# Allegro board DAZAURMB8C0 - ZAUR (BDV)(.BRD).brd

Outline 225.17 x 128 mm; copper layers: TOP, SGND, IN1, IN2, SVCC, IN3, SGND1, BOTTOM. Coordinates in mm from the lower left corner of the outline.

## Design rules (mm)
constraint set DEFAULT: min track width 0.102
net group W10-T123B: nets N17003186 N27752748
net group DFP-S3.5W4(3.5)-T13B: nets CLKA0 CLKA0B CLKA1 CLKA1B M_A_DQSN0 M_A_DQSN1 M_A_DQSN2 M_A_DQSN3 M_A_DQSN4 M_A_DQSN5 M_A_DQSN6 M_A_DQSN7 M_A_DQSP0 M_A_DQSP1 M_A_DQSP2 M_A_DQSP3 M_A_DQSP4 M_A_DQSP5 M_A_DQSP6 M_A_DQSP7 M_B_DQSN0 M_B_DQSN1 M_B_DQSN2 M_B_DQSN3 M_B_DQSN4 M_B_DQSN5 M_B_DQSN6 M_B_DQSN7 M_B_DQSP0 M_B_DQSP1 M_B_DQSP2 M_B_DQSP3 M_B_DQSP4 M_B_DQSP5 M_B_DQSP6 M_B_DQSP7 WCKA0_0 WCKA0_1 WCKA0B_0 WCKA0B_1 WCKA1_0 WCKA1_1 WCKA1B_0 WCKA1B_1
net group DFP-S4.5W4(3.5)-T13B: nets C_IN_CLK C_IN_CLK# C_IN_D0 C_IN_D0# C_IN_D1 C_IN_D1# C_IN_D2 C_IN_D2# C_TX0_HDMI+ C_TX0_HDMI- C_TX1_HDMI+ C_TX1_HDMI- C_TX2_HDMI+ C_TX2_HDMI- C_TXC_HDMI+ C_TXC_HDMI- CLK_PCIE_LANN CLK_PCIE_LANN_R CLK_PCIE_LANP CLK_PCIE_LANP_R CLK_PCIE_SSDN CLK_PCIE_SSDN_C CLK_PCIE_SSDN_R CLK_PCIE_SSDP CLK_PCIE_SSDP_C CLK_PCIE_SSDP_R CLK_PCIE_VGA_N CLK_PCIE_VGA_N_R CLK_PCIE_VGA_P CLK_PCIE_VGA_P_R CLK_PCIE_WLANN CLK_PCIE_WLANN_R CLK_PCIE_WLANP CLK_PCIE_WLANP_R GFX_TX0N_C GFX_TX0P_C GFX_TX1N_C GFX_TX1P_C GFX_TX2N_C GFX_TX2P_C GFX_TX3N_C GFX_TX3P_C IN_CLK IN_CLK# IN_D0 IN_D0# IN_D1 IN_D1# IN_D2 IN_D2# INT_EDP_AUXN INT_EDP_AUXN_C INT_EDP_AUXP INT_EDP_AUXP_C INT_EDP_TXN0 INT_EDP_TXN0_C INT_EDP_TXN1 INT_EDP_TXN1_C INT_EDP_TXN2 INT_EDP_TXN2_C INT_EDP_TXN3 INT_EDP_TXN3_C INT_EDP_TXP0 INT_EDP_TXP0_C INT_EDP_TXP1 INT_EDP_TXP1_C INT_EDP_TXP2 INT_EDP_TXP2_C INT_EDP_TXP3 INT_EDP_TXP3_C PCIE_RXN9_LAN PCIE_RXN10_WLAN PCIE_RXN13_SSD PCIE_RXN13_SSD_C PCIE_RXN14_SSD PCIE_RXN14_SSD_C PCIE_RXN15_SSD PCIE_RXN15_SSD_C PCIE_RXN16_SSD PCIE_RXN16_SSD_C PCIE_RXN_LAN_L PCIE_RXP9_LAN PCIE_RXP10_WLAN PCIE_RXP13_SSD PCIE_RXP13_SSD_C PCIE_RXP14_SSD PCIE_RXP14_SSD_C PCIE_RXP15_SSD PCIE_RXP15_SSD_C PCIE_RXP16_SSD PCIE_RXP16_SSD_C PCIE_RXP_LAN_L PCIE_TXN0_SSD_C PCIE_TXN1_SSD_C PCIE_TXN2_SSD_C PCIE_TXN3_SATA1_TXN_SSD_C PCIE_TXN6_LAN_C PCIE_TXN7_WLAN_C PCIE_TXN9_LAN PCIE_TXN10_WLAN PCIE_TXN13_SSD PCIE_TXN13_SSD_C PCIE_TXN14_SSD PCIE_TXN14_SSD_C PCIE_TXN15_SSD PCIE_TXN15_SSD_C PCIE_TXN16_SSD PCIE_TXN16_SSD_C PCIE_TXP0_SSD_C PCIE_TXP1_SSD_C PCIE_TXP2_SSD_C PCIE_TXP3_SATA1_TXP_SSD_C PCIE_TXP6_LAN_C PCIE_TXP7_WLAN_C PCIE_TXP9_LAN PCIE_TXP10_WLAN PCIE_TXP13_SSD PCIE_TXP13_SSD_C PCIE_TXP14_SSD PCIE_TXP14_SSD_C PCIE_TXP15_SSD PCIE_TXP15_SSD_C PCIE_TXP16_SSD PCIE_TXP16_SSD_C PEG_RXN0 PEG_RXN0_C PEG_RXN1 PEG_RXN1_C PEG_RXN2 PEG_RXN2_C PEG_RXN3 PEG_RXN3_C PEG_RXP0 PEG_RXP0_C PEG_RXP1 PEG_RXP1_C PEG_RXP2 PEG_RXP2_C PEG_RXP3 PEG_RXP3_C PEG_TXN0 PEG_TXN1 PEG_TXN2 PEG_TXN3 PEG_TXP0 PEG_TXP1 PEG_TXP2 PEG_TXP3 TX0_HDMI+ TX0_HDMI- TX1_HDMI+ TX1_HDMI- TX2_HDMI+ TX2_HDMI- TXC_HDMI+ TXC_HDMI- USB3_SS0RX+ USB3_SS0RX+_RE USB3_SS0RX+_RE_C USB3_SS0RX- USB3_SS0RX-_RE USB3_SS0RX-_RE_C USB3_SS0TX+ USB3_SS0TX+_RE USB3_SS0TX+_RE_C USB3_SS0TX- USB3_SS0TX-_RE USB3_SS0TX-_RE_C USB30_RX0+ USB30_RX0- USB30_RX1+ USB30_RX1+_C USB30_RX1- USB30_RX1-_C USB30_RX2+ USB30_RX2+_C USB30_RX2- USB30_RX2-_C USB30_RX+_TYPEC1 USB30_RX+_TYPEC1_C USB30_RX+_TYPEC2 USB30_RX+_TYPEC2_C USB30_RX-_TYPEC1 USB30_RX-_TYPEC1_C USB30_RX-_TYPEC2 USB30_RX-_TYPEC2_C USB30_TX0+ USB30_TX0- USB30_TX1+ USB30_TX1+_C USB30_TX1+_C_R USB30_TX1- USB30_TX1-_C USB30_TX1-_C_R USB30_TX2+ USB30_TX2+_C USB30_TX2+_C_R USB30_TX2- USB30_TX2-_C USB30_TX2-_C_R USB30_TX+_TYPEC1 USB30_TX+_TYPEC1_C USB30_TX+_TYPEC2 USB30_TX+_TYPEC2_C USB30_TX-_TYPEC1 USB30_TX-_TYPEC1_C USB30_TX-_TYPEC2 USB30_TX-_TYPEC2_C
net group DFP-S6(5)W6.5(5.5)-T13B: nets M_A_CLKN0 M_A_CLKN1 M_A_CLKP0 M_A_CLKP1 M_B_CLKN0 M_B_CLKP0
net group DFP-S6(5.5)W4(3.5)-T13B: nets SATA_RXN0_CN SATA_RXN0_HDD SATA_RXN0_IN SATA_RXN1A_C SATA_RXN1A_ODD SATA_RXN_OUT SATA_RXP0_CN SATA_RXP0_HDD SATA_RXP0_IN SATA_RXP1A_C SATA_RXP1A_ODD SATA_RXP_OUT SATA_TXN0_CN SATA_TXN0_HDD SATA_TXN0_IN SATA_TXN1A_C SATA_TXN1A_ODD SATA_TXN_OUT SATA_TXP0_CN SATA_TXP0_HDD SATA_TXP0_IN SATA_TXP1A_C SATA_TXP1A_ODD SATA_TXP_OUT USBP0+ USBP0- USBP1+ USBP1+_C USBP1+_C_R USBP1+_C_R_N USBP1+_U14 USBP1- USBP1-_C USBP1-_C_R USBP1-_C_R_N USBP1-_U14 USBP2+ USBP2+_C USBP2- USBP2-_C USBP4+_DB USBP4-_DB USBP5+_CAM USBP5+_CAM_C USBP5-_CAM USBP5-_CAM_C USBP7+_FP USBP7-_FP USBP8+_TS USBP8-_TS USBP8_TS+_C USBP8_TS-_C USBP10+_BT USBP10-_BT USBP_TYPC+_C USBP_TYPC-_C
net group DFP-S11.5(11: nets MDI0+ MDI0+_1 MDI0- MDI0-_1 MDI1+ MDI1+_1 MDI1- MDI1-_1 MDI2+ MDI2+_1 MDI2- MDI2-_1 MDI3+ MDI3+_1 MDI3- MDI3-_1
net group W4(3.5)-T13B: nets 3662AC_PWROK ACZ_BCLK_R ACZ_RST#_R ACZ_SDOUT_R ACZ_SYNC_R APU_PWRGD_D APU_PWRGD_SVID_REG APU_RST# DMIC_CLK DMIC_CLK_L DMIC_DAT DMIC_DAT_L DNBSWON# EC_PWROK HWPG M_A_DM0 M_A_DM1 M_A_DM2 M_A_DM3 M_A_DM4 M_A_DM5 M_A_DM6 M_A_DM7 M_A_DQ0 M_A_DQ1 M_A_DQ2 M_A_DQ3 M_A_DQ4 M_A_DQ5 M_A_DQ6 M_A_DQ7 M_A_DQ8 M_A_DQ9 M_A_DQ10 M_A_DQ11 M_A_DQ12 M_A_DQ13 M_A_DQ14 M_A_DQ15 M_A_DQ16 M_A_DQ17 M_A_DQ18 M_A_DQ19 M_A_DQ20 M_A_DQ21 M_A_DQ22 M_A_DQ23 M_A_DQ24 M_A_DQ25 M_A_DQ26 M_A_DQ27 M_A_DQ28 M_A_DQ29 M_A_DQ30 M_A_DQ31 M_A_DQ32 M_A_DQ33 M_A_DQ34 M_A_DQ35 M_A_DQ36 M_A_DQ37 M_A_DQ38 M_A_DQ39 M_A_DQ40 M_A_DQ41 M_A_DQ42 M_A_DQ43 M_A_DQ44 M_A_DQ45 M_A_DQ46 M_A_DQ47 M_A_DQ48 M_A_DQ49 M_A_DQ50 M_A_DQ51 M_A_DQ52 M_A_DQ53 M_A_DQ54 M_A_DQ55 M_A_DQ56 M_A_DQ57 M_A_DQ58 M_A_DQ59 M_A_DQ60 M_A_DQ61 M_A_DQ62 M_A_DQ63 M_A_EVENT# M_A_RST# M_B_DM0 M_B_DM1 M_B_DM2 M_B_DM3 M_B_DM4 M_B_DM5 M_B_DM6 M_B_DM7 M_B_DQ0 M_B_DQ1 M_B_DQ2 M_B_DQ3 M_B_DQ4 M_B_DQ5 M_B_DQ6 M_B_DQ7 M_B_DQ8 M_B_DQ9 M_B_DQ10 M_B_DQ11 M_B_DQ12 M_B_DQ13 M_B_DQ14 M_B_DQ15 M_B_DQ16 M_B_DQ17 M_B_DQ18 M_B_DQ19 M_B_DQ20 M_B_DQ21 M_B_DQ22 M_B_DQ23 M_B_DQ24 M_B_DQ25 M_B_DQ26 M_B_DQ27 M_B_DQ28 M_B_DQ29 M_B_DQ30 M_B_DQ31 M_B_DQ32 M_B_DQ33 M_B_DQ34 M_B_DQ35 M_B_DQ36 M_B_DQ37 M_B_DQ38 M_B_DQ39 M_B_DQ40 M_B_DQ41 M_B_DQ42 M_B_DQ43 M_B_DQ44 M_B_DQ45 M_B_DQ46 M_B_DQ47 M_B_DQ48 M_B_DQ49 M_B_DQ50 M_B_DQ51 M_B_DQ52 M_B_DQ53 M_B_DQ54 M_B_DQ55 M_B_DQ56 M_B_DQ57 M_B_DQ58 M_B_DQ59 M_B_DQ60 M_B_DQ61 M_B_DQ62 M_B_DQ63 PCH_AZ_CODEC_BITCLK PCH_AZ_CODEC_RST# PCH_AZ_CODEC_SDIN0 PCH_AZ_CODEC_SDIN0_R PCH_AZ_CODEC_SDOUT PCH_AZ_CODEC_SYNC PEGX_RST# PLTRST# RSMRST# SUSB# SUSC# SYS_RST# USB_OC1# USB_OC2#
net group W4(3.5)-T123B: nets 2ND_MBCLK 2ND_MBDATA 32K_X1 32K_X2 48M_X1 48M_X2 APU_DISP_ON APU_DPST_PWM APU_LVDS_BLON BRIGHT DGPUT_CLK DGPUT_CLK_R DGPUT_DATA DGPUT_DATA_R DISP_ON GPU_CLR_REQ6# GPU_EDP_HPD HDMI_HPD HDMI_HPD_CON HDMI_HPD_DC HDMI_SCLK HDMI_SDATA I2C_C0_CLK I2C_C0_DATA LAN_XTAL1 PCH_BLON_C PCIE_CLKREQ_LAN# PCIE_CLKREQ_SSD# PCIE_CLKREQ_WLAN# SI_XTALIN SI_XTALOUT SL_CLK_100M SMB_RUN_CLK SMB_RUN_DAT TP_SMB_CLK TP_SMB_DATA TPCLK TPDATA XTAL1 XTAL2 XTALIN XTALOUT
net group W4-T13B: nets APU_SPI_CLK_R1 APU_SPI_CLK_R2 APU_SPI_CS0#_R1 APU_SPI_CS0#_R2 APU_SPI_HOLD#_R2 APU_SPI_SI_R1 APU_SPI_SI_R2 APU_SPI_SO_R1 APU_SPI_SO_R2 APU_SPI_SO_TPM APU_SPI_WP_R1 APU_SPI_WP_R2 APU_SVC APU_SVD APU_SVT EC_SPI1_CLK EC_SPI1_SI EC_SPI1_SO EC_SPI_CS0# EC_SPI_HOLD# EC_SPI_WP# LAD0 LAD1 LAD2 LAD3 LPC_LAD0 LPC_LAD1 LPC_LAD2 LPC_LAD3 PROCHOT_EC SERIRQ SPI_CS#_A SPI_SCK_A SPI_SDI_A SPI_SDO_A SPI_WP_R SVC_APU SVD_APU SVT_APU
net group W5(4.5)-T13B: nets ADBIA0 ADBIA1 CASA0B CASA1B CKEA0 CKEA1 CSA0B_0 CSA1B_0 DDBIA0_0 DDBIA0_1 DDBIA0_2 DDBIA0_3 DDBIA1_0 DDBIA1_1 DDBIA1_2 DDBIA1_3 DQA0_0 DQA0_1 DQA0_2 DQA0_3 DQA0_4 DQA0_5 DQA0_6 DQA0_7 DQA0_8 DQA0_9 DQA0_10 DQA0_11 DQA0_12 DQA0_13 DQA0_14 DQA0_15 DQA0_16 DQA0_17 DQA0_18 DQA0_19 DQA0_20 DQA0_21 DQA0_22 DQA0_23 DQA0_24 DQA0_25 DQA0_26 DQA0_27 DQA0_28 DQA0_29 DQA0_30 DQA0_31 DQA1_0 DQA1_1 DQA1_2 DQA1_3 DQA1_4 DQA1_5 DQA1_6 DQA1_7 DQA1_8 DQA1_9 DQA1_10 DQA1_11 DQA1_12 DQA1_13 DQA1_14 DQA1_15 DQA1_16 DQA1_17 DQA1_18 DQA1_19 DQA1_20 DQA1_21 DQA1_22 DQA1_23 DQA1_24 DQA1_25 DQA1_26 DQA1_27 DQA1_28 DQA1_29 DQA1_30 DQA1_31 DRAM_RST_A EDCA0_0 EDCA0_1 EDCA0_2 EDCA0_3 EDCA1_0 EDCA1_1 EDCA1_2 EDCA1_3 MAA0_0 MAA0_1 MAA0_2 MAA0_3 MAA0_4 MAA0_5 MAA0_6 MAA0_7 MAA0_8 MAA1_0 MAA1_1 MAA1_2 MAA1_3 MAA1_4 MAA1_5 MAA1_6 MAA1_7 MAA1_8 RASA0B RASA1B WEA0B WEA1B
net group W6.5(5.5)-T13B: nets M_A_A0 M_A_A1 M_A_A2 M_A_A3 M_A_A4 M_A_A5 M_A_A6 M_A_A7 M_A_A8 M_A_A9 M_A_A10 M_A_A11 M_A_A12 M_A_A13 M_A_ACT# M_A_ALERT# M_A_BG#0 M_A_BG#1 M_A_BS#0 M_A_BS#1 M_A_CAS# M_A_CKE0 M_A_CKE1 M_A_CS#0 M_A_CS#1 M_A_ODT0 M_A_ODT1 M_A_PARITY M_A_RAS# M_A_WE#
net group W6.5(5.25)-T13B: nets M_B_BG#0 M_B_BG#1 M_B_BG#1_R M_B_BG#2_R M_B_BG#3_R M_B_BG#4_R M_B_BS#0 M_B_BS#1 M_B_CAS# M_B_PARITY M_B_WE#
net group W6.5(5.25)-T123B: nets M_B_A0 M_B_A1 M_B_A2 M_B_A3 M_B_A4 M_B_A5 M_B_A6 M_B_A7 M_B_A8 M_B_A9 M_B_A10 M_B_A11 M_B_A12 M_B_A13 M_B_ACT# M_B_ALERT# M_B_CKE0 M_B_CS#0 M_B_ODT0 M_B_RAS#
net group W8-T123B: nets +1.05V_LAN +5V_PVDD +5VA +AZA_CPVDD +AZA_DVDD +VREF_CA0 AVDD2 DVDD_IO
net group W15-T123B: nets HP-L2 HP-L3 HP-R2 HP-R3 HP_JD# LINE1-L LINE1-R LINE1-VREFO-L LINE1-VREFO-R MIC2-VREFO SENSEA
net group W20-T123B: nets 5447_CC1_CON 5447_CC2_CON +0.75V +1.8V_SW +3V_DMIC +3V_EC +3V_GFX +3V_LAN +3V_LDO_EC +3V_RTC +3V_RTC_0 +3V_RTC_1 +3V_RTC_2 +3V_SSD +3V_WLAN_P +3VLCD_CON +3VLCD_CON_R +3VPCU +3VPCU_EC +3VPCU_ECPLL +5V_HDMIC +5V_KB +5V_ODD +601_VCC +A3VPCU +APU_VDD_33 +APU_VDD_33_S5 +APU_VDDIO_AZ +G_SEN_PW +TYPEC_VBUS +USBPWR0 +USBPWR1 +VDD_18_S5 +VDDQ_VTT MVREFDA PBA_PWR PBA_PWR_C PBA_PWR_R VDDBT_RTC VDDP VDDP_S5 VDDQ_VTTREF VREFC_A0 VREFC_A1 VREFD1_A0 VREFD1_A1 VREFD2_A0 VREFD2_A1 VSTBY_FSPI
net group W40-T123B: nets L_SPK+ L_SPK+_1 L_SPK- L_SPK-_1 R_SPK+ R_SPK+_1 R_SPK- R_SPK-_1 RING2 SLEEVE
net group W60-T123B: nets +1.05V_LAN_REGOUT

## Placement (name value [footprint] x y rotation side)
C1  EV@0.1u/16V_4  [C0402]  117.66 124.9 270 top
C2  EV@120P/50V_4  [C0402]  124.27 121.14 0 top
C3  EV@1u/6.3V_2  [C0201]  133.03 118.1 270 top
C4  EV@0.1u/6.3V_2  [C0201]  133.89 118.1 270 top
C5  EV@0.1u/6.3V_2  [C0201]  135.06 118.1 270 top
C6  EV@1u/6.3V_2  [C0201]  147.22 117.48 0 top
C7  EV@1u/6.3V_2  [C0201]  145.67 116.74 270 top
C8  EV@0.1u/6.3V_2  [C0201]  142.94 116.45 0 top
C9  EV@1U/6.3V_4  [C0402]  139.86 116.01 180 top
C10  EV@0.22u/6.3V_2  [C0201]  96.45 115.05 0 top
C11  10u/6.3V_4  [C0402_2]  47.81 114.54 0 top
C12  *0.1u/6.3V_2  [C0201]  49.08 114.54 270 top
C13  0.1u/6.3V_2  [C0201]  49.85 114.54 270 top
C14  *0.1u/6.3V_2  [C0201]  50.61 114.54 270 top
C15  EV@1u/6.3V_2  [C0201]  148.02 114.37 270 top
C16  EV@0.22u/6.3V_2  [C0201]  96.45 114.29 0 top
C17  EV@0.22u/6.3V_2  [C0201]  96.45 113.52 0 top
C18  EV@1u/6.3V_2  [C0201]  144.71 113.42 90 top
C19  EV@0.22u/6.3V_2  [C0201]  96.45 112.76 0 top
C20  EV@0.22u/6.3V_2  [C0201]  96.45 112 0 top
C21  EV@1U/6.3V_4  [C0402]  149.03 112 0 top
C22  EV@0.1u/6.3V_2  [C0201]  145.57 111.38 0 top
C23  EV@1u/6.3V_2  [C0201]  146.62 111.38 180 top
C24  1000p/50V_4  [C0402]  57.47 111.37 180 top
C25  15p/50V_4  [C0402]  44.38 111.24 0 top
C26  15p/50V_4  [C0402]  46.19 111.24 0 top
C27  EV@0.22u/6.3V_2  [C0201]  96.45 111.24 0 top
C28  10P/50V_4  [C0402]  41.46 111.11 90 top
C29  10P/50V_4  [C0402]  42.84 111.11 90 top
C30  EV@1u/6.3V_2  [C0201]  148.96 110.98 0 top
C31  EV@1u/6.3V_2  [C0201]  107.5 110.86 90 top
C32  EV@1u/6.3V_2  [C0201]  108.27 110.86 90 top
C33  EV@1u/6.3V_2  [C0201]  109.03 110.86 90 top
C34  EV@1u/6.3V_2  [C0201]  109.76 110.86 90 top
C35  0.1u/6.3V_2  [C0201]  48.32 110.73 270 top
C36  EV@1u/6.3V_2  [C0201]  118.25 110.7 0 top
C37  EV@0.22u/6.3V_2  [C0201]  96.45 110.48 0 top
C38  EV@1u/6.3V_2  [C0201]  104.84 110.48 90 top
C39  EV@1u/6.3V_2  [C0201]  105.6 110.48 90 top
C40  EV@1u/6.3V_2  [C0201]  106.36 110.48 90 top
C41  EV@1u/6.3V_2  [C0201]  110.82 110.48 90 top
C42  EV@1u/6.3V_2  [C0201]  148.98 109.97 0 top
C43  4.7u/25V_6  [C0603]  58.48 109.84 0 top
C44  EV@0.22u/6.3V_2  [C0201]  96.45 109.71 0 top
C45  EV@0.1u/6.3V_2  [C0201]  144.77 109.57 270 top
C46  0.1u/6.3V_2  [C0201]  53.66 109.46 90 top
C47  EV@0.1u/6.3V_2  [C0201]  146.97 109.35 0 top
C48  0.1u/6.3V_2  [C0201]  43.62 109.08 0 top
C49  EV@1u/6.3V_2  [C0201]  148.98 108.95 0 top
C50  EV@22u/6.3V_6  [C0603]  118.5 108.62 180 top
C51  *4.7u/6.3V_4  [C0402_2]  40.83 108.32 90 top
C52  33p/50V_4  [C0402]  59.75 108.19 270 top
C53  EV@1u/6.3V_2  [C0201]  107.68 108.11 270 top
C54  EV@1u/6.3V_2  [C0201]  108.7 108.11 270 top
C55  EV@1u/6.3V_2  [C0201]  109.71 108.11 270 top
C56  0.1u/6.3V_2  [C0201]  41.84 108.06 90 top
C57  EV@0.1u/6.3V_2  [C0201]  148.98 107.94 0 top
C58  EV@22u/6.3V_6  [C0603]  104.74 107.86 90 top
C59  EV@22u/6.3V_6  [C0603]  106.31 107.86 270 top
C60  EV@1u/6.3V_2  [C0201]  119.19 107.05 0 top
C61  0.1u/6.3V_2  [C0201]  60.77 106.92 0 top
C62  EV@1u/6.3V_2  [C0201]  117.26 106.92 0 top
C63  EV@0.1u/6.3V_2  [C0201]  148.98 106.92 0 top
C64  EV@1u/6.3V_2  [C0201]  142.17 106.67 180 top
C65  0.1u/6.3V_2  [C0201]  40.07 106.54 270 top
C66  100p/50V_4  [C0402]  62.04 106.54 270 top
C67  1000p/50V_4  [C0402]  59.75 106.41 90 top
C68  EV@1u/6.3V_2  [C0201]  146.62 106.39 0 top
C69  EV@0.1u/6.3V_2  [C0201]  143.92 106.3 0 top
C70  0.1u/6.3V_2  [C0201]  49.85 106.16 90 top
C71  1u/6.3V_2  [C0201]  50.61 106.16 270 top
C72  0.1u/6.3V_2  [C0201]  51.37 106.16 90 top
C73  0.1u/25V_4  [C0402]  64.58 105.65 180 top
C74  0.1u/6.3V_2  [C0201]  58.48 105.52 180 top
C75  EV@1u/6.3V_2  [C0201]  143.19 105.52 0 top
C76  EV@1u/6.3V_2  [C0201]  114.95 105.32 90 top
C77  EV@1u/6.3V_2  [C0201]  116.22 105.32 90 top
C78  EV@1u/6.3V_2  [C0201]  117.36 105.32 270 top
C79  EV@1u/6.3V_2  [C0201]  145.22 105.2 0 top
C80  EV@22u/6.3V_6  [C0603]  111.59 104.86 90 top
C81  EV@22u/6.3V_6  [C0603]  113.35 104.86 90 top
C82  EV@1u/6.3V_2  [C0201]  119.19 104.76 0 top
C83  0.01u/50V_4  [C0402]  64.58 104.63 180 top
C84  EV@1u/6.3V_2  [C0201]  141.54 104.63 180 top
C85  EV@10u/6.3V_4  [C0402_2]  147.25 104.38 0 top
C86  EV@0.1u/6.3V_2  [C0201]  133.05 104.27 180 top
C87  EV@1u/6.3V_2  [C0201]  134.17 104.27 180 top
C88  EV@1u/6.3V_2  [C0201]  135.28 104.27 0 top
C89  *EV@330U_2.5V_3528  [C3528]  109 104.18 90 top
C90  0.1u/6.3V_2  [C0201]  48.32 104 0 top
C91  EV@22u/6.3V_6  [C0603]  104.84 104 270 top
C92  EV@22u/6.3V_6  [C0603]  106.36 104 270 top
C93  EV@1u/6.3V_2  [C0201]  116.09 103.92 180 top
C94  0.1u/6.3V_2  [C0201]  48.32 103.24 0 top
C95  EV@22u/6.3V_6  [C0603]  118.5 103.16 180 top
C96  0.1u/6.3V_2  [C0201]  40.57 103.11 270 top
C97  EV@1u/6.3V_2  [C0201]  142.17 102.86 180 top
C98  EV@1u/6.3V_2  [C0201]  113.93 102.48 90 top
C99  EV@1u/6.3V_2  [C0201]  115.12 102.48 90 top
C100  0.01u/50V_4  [C0402]  29.53 102.37 180 top
C101  EV@1u/6.3V_2  [C0201]  104.84 101.97 90 top
C102  EV@10u/6.3V_4  [C0402_2]  106.31 101.76 90 top
C103  TSI@4.7U/6.3V_4  [C0402]  59.88 101.59 270 top
C104  EV@1u/6.3V_2  [C0201]  118.93 101.48 0 top
C105  EV@1u/6.3V_2  [C0201]  116.98 101.38 180 top
C106  EV@0.1u/6.3V_2  [C0201]  142.43 100.83 270 top
C107  0.1u/6.3V_2  [C0201]  43.37 100.82 0 top
C108  0.1u/6.3V_2  [C0201]  60.92 100.75 180 top
C109  EV@22u/6.3V_6  [C0603]  113.73 100.34 270 top
C110  EV@22u/6.3V_6  [C0603]  115.38 100.34 90 top
C111  *4.7u/6.3V_4  [C0402_2]  43.24 99.81 0 top
C112  EV@22u/6.3V_6  [C0603]  108.62 99.68 90 top
C113  EV@22u/6.3V_6  [C0603]  110.04 99.68 90 top
C114  *22U/6.3V_6  [C0603]  60.64 99.55 180 top
C115  EV@1u/6.3V_2  [C0201]  105.6 99.55 270 top
C116  EV@1u/6.3V_2  [C0201]  106.36 99.55 270 top
C117  EV@1U/6.3V_4  [C0402]  107.25 99.55 90 top
C118  EV@0.1u/6.3V_2  [C0201]  142.43 99.4 90 top
C119  EV@1u/6.3V_2  [C0201]  117.54 98.16 180 top
C120  EV@1u/6.3V_2  [C0201]  113.09 97.52 90 top
C121  EV@1u/6.3V_2  [C0201]  108.67 97.4 90 top
C122  EV@1u/6.3V_2  [C0201]  110.04 97.4 90 top
C123  EV@1u/6.3V_2  [C0201]  110.93 97.4 90 top
C124  EV@1u/6.3V_2  [C0201]  115.89 97.14 180 top
C125  EV@22u/6.3V_6  [C0603]  96.84 97.01 90 top
C126  EV@1u/6.3V_2  [C0201]  118.43 96.89 0 top
C127  EV@10u/6.3V_4  [C0402_2]  147.04 96.76 180 top
C128  EV@1u/6.3V_2  [C0201]  114.11 96.25 180 top
C129  0.1u/6.3V_2  [C0201]  50.23 95.87 180 top
C130  *EV@0.1u/16V_4  [C0402]  90.99 95.36 90 top
C131  EV@1u/6.3V_2  [C0201]  144.59 95.36 180 top
C132  EV@1u/6.3V_2  [C0201]  145.74 95.36 180 top
C133  EV@0.1u/6.3V_2  [C0201]  143 95.36 0 top
C134  EV@10u/6.3V_4  [C0402_2]  96.07 94.98 180 top
C135  0.1u/6.3V_2  [C0201]  50.23 94.73 180 top
C136  EV@0.1u/6.3V_2  [C0201]  147.45 94.59 0 top
C137  EV@0.1u/6.3V_2  [C0201]  143.44 94.22 0 top
C138  *EV@0.1u/16V_4  [C0402]  90.87 93.97 180 top
C139  EV@1u/6.3V_2  [C0201]  145.51 93.87 90 top
C140  EV@1u/6.3V_2  [C0201]  133.57 93.36 270 top
C141  0.22u/6.3V_2  [C0201]  30.92 92.82 90 top
C142  0.22u/6.3V_2  [C0201]  32.95 92.82 90 top
C143  0.22u/6.3V_2  [C0201]  34.86 92.82 90 top
C144  0.22u/6.3V_2  [C0201]  36.76 92.82 90 top
C145  0.22u/6.3V_2  [C0201]  38.67 92.82 90 top
C146  0.22u/6.3V_2  [C0201]  40.07 92.82 90 top
C147  0.22u/6.3V_2  [C0201]  41.59 92.82 90 top
C148  EV@1u/6.3V_2  [C0201]  148.98 92.19 0 top
C149  0.1u/6.3V_2  [C0201]  44 92.06 0 top
C150  10u/6.3V_4  [C0402_2]  45.27 91.68 270 top
C151  0.01u/16V_2  [C0201]  46.29 91.68 270 top
C152  0.01u/16V_2  [C0201]  47.05 91.68 270 top
C153  1000p/25V_2  [C0201]  44 91.3 180 top
C154  EV@1u/6.3V_2  [C0201]  148.98 91.05 0 top
C155  0.22u/6.3V_2  [C0201]  27.37 89.9 180 top
C156  EV@1u/6.3V_2  [C0201]  148.98 89.9 0 top
C157  1u/6.3V_4  [C0402]  50.08 89.33 180 top
C158  EV@1u/6.3V_2  [C0201]  144.78 89.26 0 top
C159  EV@1u/6.3V_2  [C0201]  146.69 89.26 0 top
C160  EV@1u/6.3V_2  [C0201]  143.1 89.03 90 top
C161  EV@0.1u/6.3V_2  [C0201]  148.98 88.76 0 top
C162  0.22u/6.3V_2  [C0201]  27.37 88.12 180 top
C163  EV@1u/6.3V_2  [C0201]  148.98 87.62 0 top
C164  EV@1u/6.3V_2  [C0201]  145.04 87.08 0 top
C165  0.22u/6.3V_2  [C0201]  50.73 86.6 0 top
C166  EV@1u/6.3V_2  [C0201]  148.98 86.47 0 top
C167  0.22u/6.3V_2  [C0201]  27.37 86.35 180 top
C168  EV@1u/6.3V_2  [C0201]  148.98 85.33 0 top
C169  EV@1u/6.3V_2  [C0201]  144.96 85.32 180 top
C170  0.22u/6.3V_2  [C0201]  50.73 84.44 0 top
C171  EV@0.1u/6.3V_2  [C0201]  148.98 84.19 0 top
C172  EV@1u/6.3V_2  [C0201]  148.98 82.92 0 top
C173  0.22u/6.3V_2  [C0201]  27.75 82.16 180 top
C174  0.01u/16V_2  [C0201]  17.21 82.03 270 top
C175  EV@1u/6.3V_2  [C0201]  142.35 81.9 0 top
C176  EV@1u/6.3V_2  [C0201]  143.44 81.9 180 top
C177  EV@0.1u/6.3V_2  [C0201]  144.54 81.9 0 top
C178  EV@0.1u/6.3V_2  [C0201]  145.86 81.9 180 top
C179  EV@0.1u/6.3V_2  [C0201]  146.98 81.89 0 top
C180  0.22u/6.3V_2  [C0201]  50.73 81.52 0 top
C181  0.1u/6.3V_2  [C0201]  25.21 81.39 270 top
C182  0.1u/6.3V_2  [C0201]  25.97 81.39 270 top
C183  0.01u/16V_2  [C0201]  20 81.14 90 top
C184  0.1u/6.3V_2  [C0201]  20.76 81.14 90 top
C185  0.22u/6.3V_2  [C0201]  27.75 80.25 180 top
C186  22u/6.3V_6  [C0603]  95.18 79.49 180 top
C187  0.1u/6.3V_2  [C0201]  26.22 78.85 180 top
C188  0.1u/6.3V_2  [C0201]  41.34 78.85 270 top
C189  0.01u/16V_2  [C0201]  42.35 78.85 90 top
C190  0.01u/16V_2  [C0201]  50.73 78.73 180 top
C191  1u/6.3V_4  [C0402]  30.29 78.35 270 top
C192  0.01u/16V_2  [C0201]  23.56 78.22 0 top
C193  0.1u/6.3V_2  [C0201]  26.22 78.09 180 top
C194  0.01u/16V_2  [C0201]  31.3 77.96 0 top
C195  0.1u/6.3V_2  [C0201]  17.71 77.58 180 top
C196  0.1u/6.3V_2  [C0201]  23.56 77.46 0 top
C197  0.1u/6.3V_2  [C0201]  37.78 77.33 0 top
C198  1u/6.3V_4  [C0402]  46.53 77.14 180 top
C199  1000p/25V_2  [C0201]  36 76.95 90 top
C200  0.22u/6.3V_2  [C0201]  50.73 76.95 0 top
C201  0.01u/16V_2  [C0201]  17.71 76.82 180 top
C202  0.1u/6.3V_2  [C0201]  23.56 76.69 0 top
C203  0.1u/6.3V_2  [C0201]  26.22 76.44 180 top
C204  0.01u/16V_2  [C0201]  23.56 75.93 0 top
C205  0.1u/6.3V_2  [C0201]  26.22 75.68 180 top
C206  *3.3p/50V_4  [C0402]  14.03 75.3 270 top
C207  0.1u/6.3V_2  [C0201]  19.24 75.17 270 top
C208  0.1u/6.3V_2  [C0201]  23.56 75.17 0 top
C209  0.1u/6.3V_2  [C0201]  20.64 75.17 270 top
C210  0.1u/6.3V_2  [C0201]  21.4 75.17 270 top
C211  0.1u/6.3V_2  [C0201]  22.54 75.17 270 top
C212  0.01u/16V_2  [C0201]  30.54 75.04 90 top
C213  0.01u/16V_2  [C0201]  50.73 74.92 180 top
C214  0.1u/6.3V_2  [C0201]  23.56 74.41 0 top
C215  0.22u/6.3V_2  [C0201]  50.73 73.77 0 top
C216  10u/6.3V_4  [C0402_2]  23.68 73.14 90 top
C217  180p/50V_4  [C0402]  84.52 71.74 0 top
C218  180p/50V_4  [C0402]  56.45 70.73 270 top
C219  22u/6.3V_6  [C0603]  55.18 70.6 270 top
C220  10U/6.3V_4  [C0402]  52.39 70.47 90 top
C221  0.22u/6.3V_2  [C0201]  29.91 69.85 180 top
C222  22u/6.3V_6  [C0603]  87.39 69.45 180 top
C223  10U/6.3V_4  [C0402]  53.66 69.33 90 top
C224  10U/6.3V_4  [C0402]  50.48 68.31 180 top
C225  1u/6.3V_4  [C0402]  30.02 68.27 180 top
C226  22u/6.3V_6  [C0603]  88.83 68.03 0 top
C227  22u/6.3V_6  [C0603]  85.1 67.3 0 top
C228  10U/6.3V_4  [C0402]  50.48 67.04 180 top
C229  *180p/25V_2  [C0201]  60.51 67.04 90 top
C230  180p/25V_2  [C0201]  61.28 67.04 90 top
C231  1u/6.3V_4  [C0402]  88.7 66.8 0 top
C232  1u/6.3V_4  [C0402]  92.01 66.41 180 top
C233  22u/6.3V_6  [C0603]  62.42 66.28 270 top
C234  22u/6.3V_6  [C0603]  63.94 66.28 270 top
C235  1u/6.3V_4  [C0402]  65.21 66.28 270 top
C236  0.22u/6.3V_2  [C0201]  34.86 65.66 0 top
C237  0.01u/16V_2  [C0201]  36 65.66 0 top
C238  10u/6.3V_4  [C0402_2]  38.29 65.66 180 top
C239  0.22u/6.3V_2  [C0201]  44.38 65.66 0 top
C240  10u/6.3V_4  [C0402_2]  45.78 65.66 0 top
C241  0.22u/6.3V_2  [C0201]  39.94 65.53 0 top
C242  0.22u/6.3V_2  [C0201]  41.08 65.53 0 top
C243  1u/6.3V_4  [C0402]  88.7 65.51 0 top
C244  1u/6.3V_4  [C0402]  50.49 65.4 0 top
C245  1u/6.3V_4  [C0402]  91.48 64.81 180 top
C246  22u/6.3V_6  [C0603]  84.59 64.47 90 top
C247  180p/50V_4  [C0402]  95.57 64.12 270 top
C248  1u/6.3V_4  [C0402]  50.48 63.74 0 top
C249  22u/6.3V_6  [C0603]  87.25 62.59 180 top
C250  22u/6.3V_6  [C0603]  90.25 61.85 180 top
C251  22u/6.3V_6  [C0603]  93.53 61.75 0 top
C252  22u/6.3V_6  [C0603]  95.81 61.06 270 top
C253  22u/6.3V_6  [C0603]  86.74 60.55 90 top
C254  22u/6.3V_6  [C0603]  93.53 60.2 0 top
C255  1u/6.3V_4  [C0402]  49.46 60.18 0 top
C256  22u/6.3V_6  [C0603]  90.25 60.17 180 top
C257  10U/6.3V_4  [C0402]  51.75 59.8 270 top
C258  1u/6.3V_4  [C0402]  53.53 59.8 90 top
C259  10U/6.3V_4  [C0402]  56.96 59.8 270 top
C260  10U/6.3V_4  [C0402]  49.46 59.17 180 top
C261  *1.6p/50V_4  [C0402]  22.16 59.04 270 top
C262  0.22u/6.3V_2  [C0201]  25.08 58.66 0 top
C263  22u/6.3V_6  [C0603]  93.53 58.65 0 top
C264  22u/6.3V_6  [C0603]  90.48 58.52 0 top
C265  180p/50V_4  [C0402]  86.73 57.77 270 top
C266  0.22u/6.3V_2  [C0201]  25.08 57.64 0 top
C267  *1.6p/50V_4  [C0402]  22.16 57.26 90 top
C268  22u/6.3V_6  [C0603]  87.96 57.12 270 top
C269  22u/6.3V_6  [C0603]  90.48 57 0 top
C270  22u/6.3V_6  [C0603]  93.53 56.97 0 top
C271  0.22U/10V_4  [C0402]  85.14 56.95 0 top
C272  0.22u/6.3V_2  [C0201]  34.35 55.49 180 top
C273  1000p/25V_2  [C0201]  36.13 55.49 0 top
C274  0.1u/6.3V_2  [C0201]  37.53 55.49 0 top
C275  22u/6.3V_6  [C0603]  90.5 55.42 0 top
C276  22u/6.3V_6  [C0603]  93.35 55.42 180 top
C277  0.1u/6.3V_2  [C0201]  20 55.36 90 top
C278  *1.6p/50V_4  [C0402]  23.23 55.23 90 top
C279  1u/6.3V_4  [C0402]  46.54 55.23 180 top
C280  0.22u/6.3V_2  [C0201]  41.08 55.1 0 top
C281  0.22u/6.3V_2  [C0201]  42.1 55.1 180 top
C282  0.22u/6.3V_2  [C0201]  43.11 55.1 0 top
C283  0.01u/16V_2  [C0201]  44.13 55.1 0 top
C284  0.22u/6.3V_2  [C0201]  45.15 55.1 0 top
C285  0.33u/25V_2  [C0201]  21.78 54.98 0 top
C286  1000p/25V_2  [C0201]  50.23 54.85 180 top
C287  22u/6.3V_6  [C0603]  87.96 54.41 270 top
C288  0.1u/6.3V_2  [C0201]  50.23 54.09 0 top
C289  0.33u/25V_2  [C0201]  21.78 53.96 0 top
C290  22u/6.3V_6  [C0603]  95.76 53.62 270 top
C291  1u/6.3V_4  [C0402]  86.59 53.54 90 top
C292  *1.6p/50V_4  [C0402]  23.23 53.45 270 top
C293  0.01u/16V_2  [C0201]  30.67 53.2 90 top
C294  22u/6.3V_6  [C0603]  90.25 53.09 0 top
C295  22u/6.3V_6  [C0603]  92.89 53.09 0 top
C296  1u/6.3V_4  [C0402]  85.23 53 180 top
C297  1u/6.3V_4  [C0402]  54.42 52.69 90 top
C298  *0.047u/16V_4  [C0402]  50.23 52.31 0 top
C299  10U/6.3V_4  [C0402]  53.02 52.18 270 top
C300  22u/6.3V_6  [C0603]  87.41 51.95 180 top
C301  TPC@0.1u/16V_4  [C0402]  17.44 51.47 180 top
C302  22u/6.3V_6  [C0603]  92 51.05 90 top
C303  22u/6.3V_6  [C0603]  90.45 51.03 90 top
C304  22u/6.3V_6  [C0603]  96.65 50.98 90 top
C305  22u/6.3V_6  [C0603]  86.7 50.51 180 top
C306  TPC@470p/50V_4  [C0402]  17.44 50.46 180 top
C307  1u/6.3V_4  [C0402]  88.89 50.43 180 top
C308  *0.1u/6.3V_2  [C0201]  120.84 50.41 270 top
C309  22u/6.3V_6  [C0603]  93.42 50.11 90 top
C310  *180p/25V_2  [C0201]  61.91 49.64 270 top
C311  0.22U/10V_4  [C0402]  95.06 49.64 180 top
C312  1u/6.3V_4  [C0402]  60.89 49.52 90 top
C313  *0.1u/6.3V_2  [C0201]  120.84 49.39 270 top
C314  22u/6.3V_6  [C0603]  63.05 48.88 90 top
C315  22u/6.3V_6  [C0603]  64.58 48.88 90 top
C316  1u/6.3V_4  [C0402]  87.26 48.6 90 top
C317  10u/6.3V_4  [C0402_2]  50.61 48.37 180 top
C318  180p/50V_4  [C0402]  86.26 47.55 90 top
C319  0.22U/10V_4  [C0402]  65.85 47.48 270 top
C320  0.22U/10V_4  [C0402]  66.86 47.48 270 top
C321  0.22U/10V_4  [C0402]  69.4 47.48 270 top
C322  1u/6.3V_4  [C0402]  70.55 47.48 90 top
C323  22u/6.3V_6  [C0603]  68.13 47.36 90 top
C324  10u/6.3V_4  [C0402_2]  30.41 46.85 270 top
C325  TPC@1u/10V_4  [C0402]  17.46 46.57 0 top
C326  0.22u/6.3V_2  [C0201]  30.41 45.58 180 top
C327  1u/6.3V_4  [C0402]  87.06 45.2 0 top
C328  0.01u/16V_2  [C0201]  50.86 45.07 180 top
C329  1u/6.3V_4  [C0402]  30.02 44.65 180 top
C330  0.22u/6.3V_2  [C0201]  39.18 43.42 270 top
C331  0.22u/6.3V_2  [C0201]  39.94 43.42 270 top
C332  HDT@0.01u/50V_4  [C0402]  116.01 43.17 180 top
C333  0.01u/16V_2  [C0201]  44.38 43.04 0 top
C334  0.22u/6.3V_2  [C0201]  45.4 43.04 0 top
C335  1u/6.3V_4  [C0402]  46.85 42.98 180 top
C336  1000p/25V_2  [C0201]  38.03 42.91 180 top
C337  *1000p/50V_4  [C0402]  215.58 42.53 180 top
C338  0.1u/6.3V_2  [C0201]  38.03 42.15 0 top
C339  HDT@0.01u/50V_4  [C0402]  117.79 42.15 90 top
C340  0.01u/16V_2  [C0201]  30.16 41.01 90 top
C341  *0.1u/6.3V_2  [C0201]  149.67 40.88 90 top
C342  0.1u/16V_4  [C0402]  113.02 42.23 0 top
C343  HDT@0.1u/16V_4  [C0402]  116.9 40.63 180 top
C344  *0.1u/16V_4  [C0402]  113.02 40.25 180 top
C345  *1.6p/50V_4  [C0402]  21.14 38.85 270 top
C346  0.22u/6.3V_2  [C0201]  23.94 38.47 0 top
C347  1u/6.3V_4  [C0402]  101.41 38.47 0 top
C348  0.22u/6.3V_2  [C0201]  23.94 37.45 0 top
C349  *1.6p/50V_4  [C0402]  21.14 37.07 90 top
C350  1u/6.3V_4  [C0402]  98.11 36.69 270 top
C351  22u/6.3V_6  [C0603]  100.01 36.31 180 top
C352  0.01u/16V_2  [C0201]  49.59 36.18 270 top
C353  180p/50V_4  [C0402]  162.62 34.53 270 top
C354  *1.6p/50V_4  [C0402]  23.43 34.02 270 top
C355  0.01u/16V_2  [C0201]  49.59 34.02 270 top
C356  0.22u/6.3V_2  [C0201]  30.67 33.9 90 top
C357  0.33u/25V_2  [C0201]  21.91 33.64 0 top
C358  0.22u/6.3V_2  [C0201]  30.67 32.75 270 top
C359  1u/6.3V_4  [C0402]  96.71 32.75 180 top
C360  0.33u/25V_2  [C0201]  21.91 32.63 0 top
C361  0.22u/6.3V_2  [C0201]  49.97 32.37 0 top
C362  *1.6p/50V_4  [C0402]  23.43 32.24 90 top
C363  0.1u/6.3V_2  [C0201]  166.3 30.59 180 top
C364  0.1u/6.3V_2  [C0201]  169.73 32.12 90 top
C365  0.1u/6.3V_2  [C0201]  172.78 32.12 90 top
C366  *10u/6.3V_6  [C0603]  204.91 31.99 180 top
C367  *0.1u/16V_4  [C0402]  207.07 31.96 270 top
C368  1u/6.3V_4  [C0402]  93.41 31.86 0 top
C369  180p/50V_4  [C0402]  165.54 31.86 270 top
C370  0.1u/6.3V_2  [C0201]  47.3 31.73 270 top
C371  0.1u/6.3V_2  [C0201]  48.19 31.73 270 top
C372  *0.1u/6.3V_2  [C0201]  174.69 31.61 180 top
C373  180p/50V_4  [C0402]  183.2 31.23 0 top
C374  0.1u/6.3V_2  [C0201]  162.11 31.1 180 top
C375  1u/6.3V_2  [C0201]  103.44 30.97 0 top
C376  0.22u/6.3V_2  [C0201]  38.03 30.85 180 top
C377  0.01u/16V_2  [C0201]  39.05 30.85 180 top
C378  0.22u/6.3V_2  [C0201]  43.24 30.85 180 top
C379  10u/6.3V_4  [C0402_2]  45 30.66 180 top
C380  *100p/50V_4  [C0402]  101.41 30.47 90 top
C381  1u/6.3V_4  [C0402]  32.81 30.4 270 top
C382  1u/6.3V_4  [C0402]  91.65 32.63 180 top
C383  22u/6.3V_6  [C0603]  94.04 30.21 0 top
C384  0.1u/6.3V_2  [C0201]  215.71 30.21 180 top
C385  1u/6.3V_4  [C0402]  96.33 30.09 180 top
C386  10U/6.3V_4  [C0402]  47.42 30.08 270 top
C387  1u/6.3V_4  [C0402]  48.57 30.08 90 top
C388  1u/6.3V_4  [C0402]  88.07 29.83 180 top
C389  1u/6.3V_4  [C0402]  91.65 31.66 180 top
C390  470p/50V_4  [C0402]  215.83 29.2 0 top
C391  1u/6.3V_4  [C0402]  86.09 28.89 180 top
C392  1u/6.3V_4  [C0402]  88.07 28.82 180 top
C393  0.1u/6.3V_2  [C0201]  58.35 28.56 180 top
C394  *10u/6.3V_6  [C0603]  200.21 28.43 90 top
C395  0.1u/16V_4  [C0402]  215.83 28.05 0 top
C396  22u/6.3V_6  [C0603]  92.14 27.93 180 top
C397  180p/25V_2  [C0201]  58.35 27.67 0 top
C398  22u/6.3V_6  [C0603]  85.02 27.67 180 top
C399  22u/6.3V_6  [C0603]  87.67 27.55 180 top
C400  180p/50V_4  [C0402]  183.2 27.55 180 top
C401  10u/6.3V_4  [C0402_2]  197.8 27.55 0 top
C402  0.1u/6.3V_2  [C0201]  58.35 26.78 180 top
C403  *27p/50V_4  [C0402]  101.15 26.78 180 top
C404  *0.1u/6.3V_2  [C0201]  105.34 26.78 90 top
C405  *10U/6.3V_4  [C0402]  56.08 26.69 270 top
C406  1u/6.3V_4  [C0402]  57.22 26.69 90 top
C407  0.1u/6.3V_2  [C0201]  182.81 26.4 90 top
C408  0.1u/6.3V_2  [C0201]  183.58 26.4 90 top
C409  *0.1u/16V_4  [C0402]  200.21 26.15 90 top
C410  PBA@0.01u/50V_4  [C0402]  52.51 25.51 180 top
C411  EV@0.47u/6.3V_2  [C0201]  92.21 25.26 180 top
C412  0.1u/6.3V_2  [C0201]  163.38 25.26 90 top
C413  *0.1u/16V_4  [C0402]  105.22 25.01 180 top
C414  PBA@4.7u/6.3V_4  [C0402_2]  51.5 24.37 180 top
C415  *0.1u/16V_4  [C0402]  185.48 24.37 90 top
C416  180p/50V_4  [C0402]  183.96 24.24 0 top
C417  TPM@10u/6.3V_4  [C0402_2]  130.87 24.12 90 top
C418  0.1u/16V_4  [C0402]  162.88 23.74 0 top
C419  TPM@0.1u/6.3V_2  [C0201]  129.86 23.48 90 top
C420  TPC@22u/6.3V_6  [C0603]  17.21 23.35 270 top
C421  TPC@10u/6.3V_6  [C0603]  18.73 23.35 270 top
C422  TPC@10u/6.3V_6  [C0603]  20.25 23.35 270 top
C423  GS@0.1u/6.3V_2  [C0201]  64.2 23.02 0 top
C424  180p/50V_4  [C0402]  183.58 22.85 270 top
C425  *10p/50V_4  [C0402]  161.1 22.97 180 top
C426  *0.1u/16V_4  [C0402]  151.83 21.83 180 top
C427  1u/6.3V_2  [C0201]  163.13 21.7 270 top
C428  1000p/50V_4  [C0402]  116.39 21.35 270 top
C429  1000p/50V_4  [C0402]  117.36 21.35 270 top
C430  1000p/50V_4  [C0402]  118.38 21.35 270 top
C431  1000p/50V_4  [C0402]  119.37 21.35 270 top
C432  TPM@0.1u/6.3V_2  [C0201]  120.97 21.07 180 top
C433  *10P/50V_4  [C0402]  70.93 20.81 0 top
C434  *10P/50V_4  [C0402]  72.83 20.81 180 top
C435  TPC@0.1u/16V_4  [C0402]  9.59 20.56 270 top
C436  0.01u/10V_2  [C0201]  209.23 20.43 90 top
C437  0.01u/10V_2  [C0201]  209.99 20.43 90 top
C438  0.01u/10V_2  [C0201]  210.75 20.43 90 top
C439  0.01u/10V_2  [C0201]  211.52 20.43 90 top
C440  TPM@0.1u/6.3V_2  [C0201]  121.22 20.31 180 top
C441  *1u/6.3V_4  [C0402]  202.37 20.31 270 top
C442  TPM@10u/6.3V_4  [C0402_2]  130.62 20.05 270 top
C443  180p/50V_4  [C0402]  161.48 18.02 90 top
C444  *TPC@0.1u/6.3V_2  [C0201]  23.18 19.8 0 top
C445  TPM@0.1u/6.3V_2  [C0201]  129.6 19.54 270 top
C446  0.22U/10V_4  [C0402]  152.08 19.67 90 top
C447  TPC@10u/6.3V_4  [C0402_2]  20.51 19.54 180 top
C448  0.1u/6.3V_2  [C0201]  183.32 18.91 90 top
C449  GS@10u/6.3V_4  [C0402_2]  61.91 18.55 0 top
C450  TPC@22u/6.3V_6  [C0603]  22.79 18.53 180 top
C451  0.1u/6.3V_2  [C0201]  212.81 18.53 90 top
C452  0.1u/6.3V_2  [C0201]  213.55 18.53 90 top
C453  TPC@0.33u/25V_2  [C0201]  14.64 18.4 0 top
C454  0.1u/6.3V_2  [C0201]  164.02 18.27 270 top
C455  ODD@0.01u/50V_4  [C0402]  133.28 17.77 270 top
C456  ODD@0.01u/50V_4  [C0402]  134.3 17.77 270 top
C457  ODD@0.01u/50V_4  [C0402]  135.32 17.77 270 top
C458  ODD@0.01u/50V_4  [C0402]  136.33 17.77 270 top
C459  0.1u/6.3V_2  [C0201]  213.93 17.64 0 top
C460  TPC@0.33u/25V_2  [C0201]  14.64 17.41 0 top
C461  220p/25V_2  [C0201]  148.78 17.26 90 top
C462  220p/25V_2  [C0201]  149.54 17.26 90 top
C463  220p/25V_2  [C0201]  150.43 17.26 90 top
C464  220p/25V_2  [C0201]  151.32 17.26 90 top
C465  220p/25V_2  [C0201]  152.21 17.26 90 top
C466  220p/25V_2  [C0201]  153.1 17.26 90 top
C467  220p/25V_2  [C0201]  153.99 17.26 90 top
C468  220p/25V_2  [C0201]  154.87 17.26 90 top
C469  220p/25V_2  [C0201]  155.76 17.26 90 top
C470  220p/25V_2  [C0201]  156.65 17.26 90 top
C471  220p/25V_2  [C0201]  157.54 17.26 90 top
C472  220p/25V_2  [C0201]  158.43 17.26 90 top
C473  220p/25V_2  [C0201]  159.32 17.26 90 top
C474  220p/25V_2  [C0201]  160.21 17.26 90 top
C475  220p/25V_2  [C0201]  162.37 17.26 90 top
C476  220p/25V_2  [C0201]  163.13 17.26 90 top
C477  220p/25V_2  [C0201]  164.02 17.26 90 top
C478  GS@33p/50V_4  [C0402]  68.51 17.13 180 top
C479  0.1u/6.3V_2  [C0201]  215.61 17.13 270 top
C480  *10u/6.3V_4  [C0402_2]  216.85 16.75 180 top
C481  TPC@0.33u/25V_2  [C0201]  14.54 16.39 0 top
C482  10u/6.3V_4  [C0402_2]  216.85 15.48 180 top
C483  TPC@0.33u/25V_2  [C0201]  14.54 15.43 0 top
C484  10u/6.3V_6  [C0603]  183.32 15.35 270 top
C485  GS@0.1u/6.3V_2  [C0201]  63.82 15.23 180 top
C486  GS@33p/50V_4  [C0402]  65.21 14.79 0 top
C487  ODD@180p/50V_4  [C0402]  125.92 15.23 0 top
C488  **ODD@0.1u/16V_4  [C0402]  148.52 15.1 270 top
C489  *ODD@15p/50V_4  [C0402]  128.08 14.77 90 top
C490  *ODD@0.1u/16V_4  [C0402]  129.09 14.85 270 top
C491  *ODD@0.1u/16V_4  [C0402]  130.11 14.85 270 top
C492  ODD@0.01u/50V_4  [C0402]  131.13 14.85 270 top
C493  ODD@0.01u/50V_4  [C0402]  132.14 14.85 270 top
C494  *ODD@0.1u/16V_4  [C0402]  133.16 14.85 90 top
C495  ODD@10u/6.3V_6  [C0603]  134.43 14.46 90 top
C496  *ODD@100u/6.3V_12  [C1206]  139 14.21 180 top
C497  *MS@0.1u/16V_4  [C0402]  216.85 14.34 180 top
C498  0.1u/6.3V_2  [C0201]  207.83 13.7 0 top
C499  TPC@220p/25V_2  [C0201]  23.3 13.58 0 top
C500  TPC@0.1u/16V_4  [C0402]  10.22 13.45 90 top
C501  180p/50V_4  [C0402]  183.2 13.45 180 top
C502  *390P/50V_4  [C0402]  197.37 13.52 90 top
C503  *MS@10u/6.3V_4  [C0402]  185.23 12.94 0 top
C504  0.1u/6.3V_2  [C0201]  207.83 12.81 0 top
C505  0.01u/10V_2  [C0201]  209.1 12.56 90 top
C506  0.01u/10V_2  [C0201]  209.87 12.56 90 top
C507  0.01u/10V_2  [C0201]  210.63 12.56 90 top
C508  0.01u/10V_2  [C0201]  211.39 12.56 90 top
C509  TPC@0.1u/6.3V_2  [C0201]  22.92 12.18 180 top
C510  0.1u/6.3V_2  [C0201]  174.18 11.92 270 top
C511  TPC@0.22u/6.3V_2  [C0201]  17.97 11.67 90 top
C512  TPC@0.22u/6.3V_2  [C0201]  18.73 11.67 90 top
C513  TPC@0.22u/6.3V_2  [C0201]  19.49 11.67 90 top
C514  TPC@0.22u/6.3V_2  [C0201]  20.25 11.67 90 top
C515  TPC@220p/25V_2  [C0201]  21.14 11.67 270 top
C516  10u/6.3V_4  [C0402_2]  207.45 11.67 180 top
C517  **MS@0.1u/16V_4  [C0402]  203.26 11.16 270 top
C518  *SSD@10U/6.3V_4  [C0402]  14.29 10.4 180 top
C519  *SSD@1000p/50V_4  [C0402]  16.17 9.64 180 top
C528  SSD@4.7U/6.3V_4  [C0402]  12.13 5.17 180 top
C529  SSD@0.1u/6.3V_2  [C0201]  13.78 4.94 270 top
C530  SSD@10u/6.3V_4  [C0402]  37.15 4.94 270 top
C531  SSD@0.1u/6.3V_2  [C0201]  36.13 4.56 90 top
C532  SSD@0.1u/6.3V_2  [C0201]  38.16 4.56 90 top
C533  SSD@0.1u/6.3V_2  [C0201]  21.78 2.53 180 top
C534  SSD@0.1u/6.3V_2  [C0201]  22.92 2.53 0 top
C535  EV@10P/50V_4  [C0402]  103.06 122.41 0 bottom
C536  EV@10P/50V_4  [C0402]  105.85 122.41 180 bottom
C537  0.1u/6.3V_2  [C0201]  37.7 122.36 90 bottom
C538  *0.1u/6.3V_2  [C0201]  35.62 121.78 270 bottom
C539  *EV@0.1u/16V_4  [C0402]  59.12 121.02 0 bottom
C540  EV@0.1u/16V_4  [C0402]  102.04 121.02 270 bottom
C541  EV@10u/6.3V_4  [C0402_2]  101.03 119.24 90 bottom
C542  EV@1u/6.3V_2  [C0201]  130.67 115.49 90 bottom
C543  *R18M-50@0.082u/16V_4  [C0402]  96.71 114.54 180 bottom
C544  10p/3KV_1808  [C1808]  21.4 112.51 234 bottom
C545  EV@1U/6.3V_4  [C0402]  130.11 112.38 180 bottom
C546  *R18M-50@0.082u/16V_4  [C0402]  96.76 109.33 180 bottom
C547  *R18M-50@0.082u/16V_4  [C0402]  96.71 106.67 0 bottom
C548  0.1u/6.3V_2  [C0201]  48.07 105.4 90 bottom
C549  0.1u/6.3V_2  [C0201]  48.83 105.4 90 bottom
C550  0.1u/6.3V_2  [C0201]  49.59 105.4 90 bottom
C551  0.1u/6.3V_2  [C0201]  50.35 105.4 90 bottom
C552  0.1u/6.3V_2  [C0201]  51.12 105.4 90 bottom
C553  0.1u/6.3V_2  [C0201]  51.88 105.4 90 bottom
C554  0.1u/6.3V_2  [C0201]  52.64 105.4 90 bottom
C555  0.1u/6.3V_2  [C0201]  53.4 105.4 90 bottom
C556  180p/50V_4  [C0402]  56.2 103.87 270 bottom
C557  180p/50V_4  [C0402]  57.21 103.87 270 bottom
C558  180p/50V_4  [C0402]  58.35 103.87 270 bottom
C559  0.1u/6.3V_2  [C0201]  48.96 103.49 90 bottom
C560  0.1u/6.3V_2  [C0201]  54.04 102.35 90 bottom
C561  0.1u/6.3V_2  [C0201]  55.18 102.35 90 bottom
C562  EV@10u/6.3V_4  [C0402_2]  144.09 102.11 0 bottom
C563  *R18M-50@0.082u/16V_4  [C0402]  96.71 101.59 0 bottom
C564  *EV@1u/6.3V_2  [C0201]  94.42 98.16 0 bottom
C565  *EV@1u/6.3V_2  [C0201]  95.57 98.16 0 bottom
C566  EV@10u/6.3V_4  [C0402_2]  138.6 97.39 0 bottom
C567  10u/6.3V_4  [C0402]  64.07 94.73 0 bottom
C568  0.01u/16V_2  [C0201]  65.72 94.73 0 bottom
C569  0.1u/6.3V_2  [C0201]  64.2 93.71 180 bottom
C570  1u/6.3V_2  [C0201]  64.32 91.17 270 bottom
C571  EV@1U/6.3V_4  [C0402]  130.36 88.89 180 bottom
C572  2200P/50V_4  [C0402]  99.5 84.44 180 bottom
C573  1u/6.3V_2  [C0201]  22.92 83.04 90 bottom
C574  220p/50V_4  [C0402]  13.78 82.41 270 bottom
C575  0.1u/6.3V_2  [C0201]  17.21 82.03 270 bottom
C576  *27p/50V_4  [C0402]  83.88 81.39 180 bottom
C577  *27p/50V_4  [C0402]  86.04 81.39 0 bottom
C578  1u/6.3V_4  [C0402]  92.26 80.71 0 bottom
C579  *220p/50V_4  [C0402]  13.73 80.5 90 bottom
C580  *27p/50V_4  [C0402]  83.12 80 90 bottom
C581  EV@1U/6.3V_4  [C0402]  147.28 79.61 270 bottom
C582  EV@1U/6.3V_4  [C0402]  141.06 79.48 270 bottom
C583  1u/6.3V_4  [C0402]  92.26 79.39 0 bottom
C584  1u/6.3V_4  [C0402]  95.18 78.85 180 bottom
C585  180p/50V_4  [C0402]  92.26 78.09 0 bottom
C586  1u/6.3V_4  [C0402]  95.18 77.84 180 bottom
C587  0.22u/6.3V_2  [C0201]  106.61 77.71 180 bottom
C588  1u/6.3V_4  [C0402]  92.26 77.08 0 bottom
C589  0.22u/6.3V_2  [C0201]  106.61 76.95 180 bottom
C590  0.22u/6.3V_2  [C0201]  106.61 76.06 180 bottom
C591  0.22u/6.3V_2  [C0201]  106.61 75.3 180 bottom
C592  0.22u/6.3V_2  [C0201]  106.61 74.41 180 bottom
C593  0.22u/6.3V_2  [C0201]  106.61 73.65 180 bottom
C594  0.22u/6.3V_2  [C0201]  108.39 73.52 180 bottom
C595  10u/6.3V_4  [C0402_2]  23.68 73.14 90 bottom
C596  0.22u/6.3V_2  [C0201]  108.39 72.76 180 bottom
C597  0.22u/6.3V_2  [C0201]  106.61 72.5 180 bottom
C598  0.22u/6.3V_2  [C0201]  106.61 71.74 180 bottom
C599  0.22u/6.3V_2  [C0201]  108.14 71.23 180 bottom
C600  0.22u/6.3V_2  [C0201]  108.14 70.34 180 bottom
C601  0.22u/6.3V_2  [C0201]  108.14 69.46 180 bottom
C602  0.22u/6.3V_2  [C0201]  108.14 68.57 180 bottom
C603  0.22u/6.3V_2  [C0201]  108.14 67.68 180 bottom
C604  0.22u/6.3V_2  [C0201]  108.14 66.79 180 bottom
C605  0.1u/6.3V_2  [C0201]  108.14 65.9 0 bottom
C606  0.1u/6.3V_2  [C0201]  108.14 65.01 0 bottom
C607  0.1u/6.3V_2  [C0201]  108.14 64.12 0 bottom
C608  0.1u/6.3V_2  [C0201]  108.14 63.23 0 bottom
C609  TPC@100u/6.3V_12  [C1206]  17.64 49.64 270 bottom
C610  15p/50V_4  [C0402]  113.5 47.41 0 top
C611  *1u/16V_4  [C0402]  111.74 44.06 270 bottom
C612  *27p/50V_4  [C0402]  105.98 43.55 180 bottom
C613  470p/50V_4  [C0402]  16.19 43.17 180 bottom
C614  1u/6.3V_2  [C0201]  22.79 43.04 0 bottom
C615  *HDT@0.01u/50V_4  [C0402]  110.39 42.89 180 bottom
C616  *27p/50V_4  [C0402]  105.98 42.53 180 bottom
C617  0.1u/6.3V_2  [C0201]  16.19 42.28 0 bottom
C618  100u/6.3V_12  [C1206]  20.03 41.39 0 bottom
C619  18p/50V_4  [C0402]  105.98 41.01 0 bottom
C620  100p/50V_4  [C0402]  209.1 38.59 180 bottom
C621  100p/50V_4  [C0402]  210.88 38.59 180 bottom
C622  18p/50V_4  [C0402]  105.98 38.21 0 bottom
C623  0.01u/16V_2  [C0201]  17.59 37.76 180 bottom
C624  3.9P/50V_4  [C0402]  105.09 36.82 180 bottom
C625  3.9P/50V_4  [C0402]  108.14 36.82 0 bottom
C626  4.7u/6.3V_6  [C0603]  206.44 35.67 270 bottom
C627  *22p/50V_4  [C0402]  159.32 35.29 180 bottom
C628  *0.1u/16V_4  [C0402]  203.13 35.17 270 bottom
C629  100p/50V_4  [C0402]  210.63 35.17 0 bottom
C630  150p/50V_4  [C0402]  104.05 34.78 180 bottom
C631  4.7u/6.3V_6  [C0603]  207.96 34.53 270 bottom
C632  0.1u/6.3V_2  [C0201]  158.81 34.4 180 bottom
C633  0.1u/6.3V_2  [C0201]  21.27 34.28 90 bottom
C634  150p/50V_4  [C0402]  94.75 33.9 90 bottom
C635  10P/50V_4  [C0402]  95.82 33.9 90 bottom
C636  100p/50V_4  [C0402]  201.74 33.72 180 bottom
C637  100p/50V_4  [C0402]  210.63 33.26 0 bottom
C638  5.6P/50V_4  [C0402]  89.22 32.63 90 bottom
C639  256@0.1u/16V_4  [C0402]  202.12 32.24 270 bottom
C640  10u/6.3V_4  [C0402_2]  203.39 32.24 270 bottom
C641  10u/6.3V_4  [C0402_2]  207.07 31.96 270 bottom
C642  0.1u/6.3V_2  [C0201]  208.09 31.86 270 bottom
C643  *255@0.1u/16V_4  [C0402]  198.92 31.25 270 bottom
C644  10u/6.3V_4  [C0402_2]  192.97 31.36 90 bottom
C645  0.1u/6.3V_2  [C0201]  193.48 29.96 0 bottom
C646  10u/6.3V_4  [C0402_2]  208.72 29.83 180 bottom
C647  *100u/6.3V_12  [C1206]  210.75 29.83 90 bottom
C648  0.1u/6.3V_2  [C0201]  193.48 29.07 0 bottom
C649  22u/6.3V_6  [C0603]  84.14 28.31 180 bottom
C650  0.1u/6.3V_2  [C0201]  197.8 28.05 0 bottom
C651  2.2u/6.3V_4  [C0402]  208.72 27.67 0 bottom
C652  10u/6.3V_4  [C0402_2]  197.55 26.28 0 bottom
C653  *22p/50V_4  [C0402]  197.55 25.13 180 bottom
C654  22u/6.3V_6  [C0603]  211.52 24.75 180 bottom
C655  1u/25V_6  [C0603]  208.44 24.73 180 bottom
C656  TPC@22u/6.3V_6  [C0603]  24.45 24.12 270 bottom
C657  *TPC@47u/6.3V_8  [C0805]  20.51 23.74 270 bottom
C658  TPC@47u/6.3V_8  [C0805]  22.67 23.74 270 bottom
C659  33p/50V_4  [C0402]  197.01 23.74 270 bottom
C660  TPC@10u/25V_8  [C0805]  11.75 23.48 180 bottom
C661  10P/50V_4  [C0402]  73.34 23.99 270 bottom
C662  10P/50V_4  [C0402]  74.46 23.35 270 bottom
C663  0.1u/6.3V_2  [C0201]  76.64 23.35 270 bottom
C664  0.1u/6.3V_2  [C0201]  199.07 23.23 180 bottom
C665  10u/6.3V_6  [C0603]  207.33 22.59 90 bottom
C666  1u/25V_6  [C0603]  208.75 22.59 90 bottom
C667  *10p/50V_4  [C0402]  165.92 21.7 270 bottom
C668  *PBA@0.01u/50V_4  [C0402]  49.16 21.91 270 bottom
C669  10u/6.3V_4  [C0402_2]  199.45 21.78 180 bottom
C670  10u/6.3V_4  [C0402_2]  205.88 21.7 90 bottom
C671  TPC@0.1u/6.3V_2  [C0201]  12.51 21.55 270 bottom
C672  TPC@0.1u/6.3V_2  [C0201]  13.47 21.55 270 bottom
C673  *TPC@0.1u/6.3V_2  [C0201]  14.44 21.55 270 bottom
C674  10u/6.3V_4  [C0402_2]  204.4 21.45 180 bottom
C675  0.1u/6.3V_2  [C0201]  200.85 21.07 0 bottom
C676  0.1u/6.3V_2  [C0201]  163.13 20.69 270 top
C677  10u/6.3V_4  [C0402_2]  201.99 20.31 90 bottom
C678  0.1u/6.3V_2  [C0201]  203.01 20.31 90 bottom
C679  10u/6.3V_4  [C0402_2]  200.47 20.05 0 bottom
C680  TPC@4.7U/6.3V_4  [C0402]  19.24 19.8 90 bottom
C681  TPC@0.1u/6.3V_2  [C0201]  20.25 19.8 270 bottom
C682  TPC@0.1u/16V_4  [C0402]  21.27 19.8 270 bottom
C683  220p/25V_2  [C0201]  165.03 19.16 90 bottom
C684  220p/25V_2  [C0201]  166.05 19.16 90 bottom
C685  220p/25V_2  [C0201]  167.07 19.16 90 bottom
C686  220p/25V_2  [C0201]  168.08 19.16 90 bottom
C687  220p/25V_2  [C0201]  168.97 19.16 90 bottom
C688  220p/25V_2  [C0201]  169.99 19.16 90 bottom
C689  220p/25V_2  [C0201]  171 19.16 90 bottom
C690  220p/25V_2  [C0201]  172.02 19.16 90 bottom
C691  220p/25V_2  [C0201]  172.91 19.16 90 bottom
C692  *TPC@390p/50V_4  [C0402]  10.6 18.78 90 bottom
C693  1u/6.3V_2  [C0201]  210.12 18.53 0 bottom
C694  TPC@0.1u/6.3V_2  [C0201]  15.3 18.4 270 bottom
C695  TPC@0.1u/6.3V_2  [C0201]  16.06 18.4 270 bottom
C696  TPC@0.1u/6.3V_2  [C0201]  17.21 18.4 270 bottom
C697  TPC@0.1u/6.3V_2  [C0201]  17.97 18.4 270 bottom
C698  *PBA@2.2u/6.3V_6  [C0603]  52.39 18.66 0 bottom
C699  *KBL@2.2u/6.3V_6  [C0603]  198.69 18.15 180 bottom
C700  *0.1u/6.3V_2  [C0201]  177.99 18.91 0 bottom
C701  *10p/50V_4  [C0402]  179.89 15.1 270 bottom
C702  TPC@0.1u/6.3V_2  [C0201]  13.4 13.58 270 bottom
C703  TPC@0.1u/6.3V_2  [C0201]  14.16 13.58 270 bottom
C704  *TPC@390p/50V_4  [C0402]  10.22 13.45 270 bottom
C705  TPC@0.1u/6.3V_2  [C0201]  16.7 13.32 270 bottom
C706  TPC@0.1u/6.3V_2  [C0201]  17.46 13.32 270 bottom
C707  0.01u/16V_2  [C0201]  192.85 12.31 270 bottom
C708  0.1u/6.3V_2  [C0201]  193.74 12.31 90 bottom
C709  10u/6.3V_4  [C0402_2]  195.36 12.15 0 bottom
C710  KBL@4.7u/6.3V_6  [C0603]  197.29 11.42 270 bottom
C711  KBL@0.01u/50V_4  [C0402]  198.56 11.42 270 bottom
C712  0.01u/16V_2  [C0201]  191.96 11.16 90 bottom
C713  0.1u/6.3V_2  [C0201]  192.72 11.16 270 bottom
C714  4.7U/6.3V_4  [C0402]  194.12 11.04 0 bottom
CN1  *50208-00401-V02  [50208-00401-V02-4P-L]  35.1 118.05 0 bottom
CN2  196538-40041-3  [196538-40041-3-40P-L]  53.47 110.3 0 bottom
CN3  2RJ1622-001111F  [RJ45-2RJ1622-001111F-8P]  10.05 96.2 90 bottom
CN4  10444-19001  [HDMI-10591-19001-19P]  3.4 76.2 90 bottom
CN5  D4AS0-26010-1P40  [DDR4-D4AS0-26001-1P40-STD-SMT]  54.35 62.83 270 bottom
CN6  USB3.0 CONN  [UB3-USB-097-1R09HG-9P]  7.4 54.44 90 bottom
CN7  *HDT@HDT CONN  [ASP-137098-05-20P-LDV]  115.89 45.45 270 bottom
CN8  CF34302D0RA-05-NH  [CF34302D0RA-05-NH-30P-L]  218.95 35.65 270 bottom
CN9  USB3.0 CONN  [UB3-USB-097-1R09HG-9P]  7.4 34.44 90 bottom
CN10  *FOR14@196153-28021-35  [50584-0280N-V02-28P-L]  140.57 24.2 180 bottom
CN11  NASE0-S6701-TS40  [NGFF-NASE0-S6701-TS40-KE-SMT]  188.5 21.88 270 bottom
CN12  51653-0080N-V02  [196047-08021-3-8P-L]  72.82 18.56 180 bottom
CN13  PBA@196241-08021-3  [196241-08021-3-8P-L]  58.7 18.17 180 bottom
CN14  51325-00401-001  [51325-00401-001-4P-L]  117.8 17.6 180 bottom
CN15  TPC@UCF3M-01N01-0P53  [UB31-UCF3M-01N01-0P53-24P]  7.26 15.9 90 bottom
CN16  FOR15@196153-28021-35  [50584-0280N-V02-28P-L]  161.5 15.4 180 bottom
CN17  ODD@132F18-100000-A2-R  [132F18-100000-A2-R-18P-L]  132.6 14.35 180 bottom
CN18  KBL@50505-00401-v01-4p-l  [50505-00401-V01-4P-L]  204.32 10.95 180 bottom
CN19  SSD@NASM0-S6701-TSH4  [NGFF-NASM0-S6701-TSH4-KM-SMT]  30.6 4.35 180 bottom
CN20  50281-00201-001  [50281-00201-001-2P-L]  14.3 3.45 180 bottom
D1  *EV@SDM20U30-7  [D-1_2X0_8-0_7H]  130.74 122.29 90 top
D2  EV@SDM20U30-7  [D-1_2X0_8-0_7H]  132.27 122.29 90 top
D3  EV@SDM20U30-7  [D-1_2X0_8-0_7H]  126.93 121.4 270 top
D4  1N4148WS  [D-SOD323-1_85X1_25-0_95H]  54.16 106.52 0 top
D5  SDM20U30-7  [D-1_2X0_8-0_7H]  114.59 40.96 90 top
D6  TVM0G5R5M220R_22p  [R0402]  161.61 34.53 270 top
D7  BAT54CW  [SOT23-1_7-65-3P]  103.69 29.09 0 top
D8  RB500V-40  [D-1_85X1_25-2P-0_95H]  186.22 29.96 270 top
D9  *TPM@PESD5V0F1BL  [R0402]  131.13 21.83 0 top
D10  GS@RB500V-40  [D-SOD323-1_85X1_25-0_95H]  63.82 21.73 0 top
D11  GS@RB500V-40  [D-SOD323-1_85X1_25-0_95H]  67.5 21.7 180 top
D12  *SDM20U30-7  [D-1_2X0_8-0_7H]  155 20.69 270 top
D13  SDM20U30-7  [D-1_2X0_8-0_7H]  156.42 20.69 270 top
D14  RB500V-40  [D-SOD323-1_85X1_25-0_95H]  158.18 19.67 270 top
D15  RB500V-40  [D-SOD323-1_85X1_25-0_95H]  202.68 16.88 90 top
D16  *MS@RB500V-40  [D-SOD323-1_85X1_25-0_95H]  198.94 16.88 270 top
D17  *MS@RB500V-40  [D-SOD323-1_85X1_25-0_95H]  200.82 16.88 270 top
D18  SDM20U30-7  [D-1_2X0_8-0_7H]  152.26 14.46 90 top
D19  *SDM20U30-7  [D-1_2X0_8-0_7H]  153.68 14.46 90 top
D20  *SDM20U30-7  [D-1_2X0_8-0_7H]  155.31 14.46 90 top
D21  *SDM20U30-7  [D-1_2X0_8-0_7H]  156.93 14.46 90 top
D22  *SDM20U30-7  [D-1_2X0_8-0_7H]  158.56 14.46 90 top
D23  *SDM20U30-7  [D-1_2X0_8-0_7H]  158.66 11.92 180 top
D24  TPC@EGA10402V05AH_0.2p  [R0402]  11.62 13.65 0 top
D25  SSD@RB500V-40  [D-1_85X1_25-2P-0_95H]  33.46 3.82 270 top
D26  *ESD5451N-2/TR  [R0402]  36.51 121.53 90 bottom
D27  *ESD5451N-2/TR  [R0402]  37.55 120.97 90 bottom
D28  1N4148WS  [D-SOD323-1_85X1_25-0_95H]  114.87 35.9 90 bottom
D29  1N4148WS  [D-SOD323-1_85X1_25-0_95H]  116.75 36.13 90 bottom
D30  1N4148WS  [D-SOD323-1_85X1_25-0_95H]  118.63 36.13 90 bottom
D31  1N4148WS  [D-SOD323-1_85X1_25-0_95H]  197.17 33.08 180 bottom
D32  1N4148WS  [D-SOD323-1_85X1_25-0_95H]  195.82 31.2 180 bottom
D33  *RB500V-40  [D-SOD323-1_85X1_25-0_95H]  194.09 20.59 90 bottom
D34  AZ5725-01F.R7G  [ESD-1X0_6-2P]  171.89 21.32 90 bottom
D35  TPC@EGA10402V05AH_0.2p  [R0402]  9.59 18.78 90 bottom
D36  TPC@EGA10402V05AH_0.2p  [R0402]  11.62 18.78 270 bottom
D37  *VPORT_0603_220K-V05  [R0603]  175.58 19.29 180 bottom
D38  TPC@EGA10402V05AH_0.2p  [R0402]  11.24 13.45 270 bottom
EC1  *PBA@AZ5725-01F.R7G  [ESD-1X0_6-2P]  56.58 22.52 0 bottom
EC2  *PBA@AZ5725-01F.R7G  [ESD-1X0_6-2P]  58.74 22.52 0 bottom
EC3  TPC@22u/6.3V_6  [C0603]  10.6 21.2 0 bottom
FAN1  50278-00401-001  [WTB-50278-00401-V01-4P-L]  174.73 29.5 90 bottom
FB1  EV@BLM03AX121SN1D  [R0201]  103.14 121.19 180 bottom
HD1  51625-01201-001  [51625-01201-001-12P-L]  217.53 13.57 270 bottom
HE1  FOR15@APX8132AI-TRG  [SOT23-2_38-95-3P]  34.9 122.75 90 top
HE2  *FOR14@APX8132AI-TRG  [SOT23-2_38-95-3P]  45.3 122.75 90 top
HOLE1  *SPAD-A3A5-EDADOC-1  [SPAD-A3A5-EDADOC-1]  63.15 126.75 0 top
HOLE2  *HG-Z8E-EDADOC-1  [HG-Z8E-EDADOC-1]  148.07 124.5 0 top
HOLE3  *SPAD-RE5_98X2_0  [SPAD-RE5_98X2_0]  40.01 123.9 0 top
HOLE4  *2D-BARCODE-8X8-S  [2D-BARCODE-8X8-S]  20.56 109.61 270 top
HOLE5  *H-TC154IC154BC237D154PT-1  [H-TC154IC154BC237D154PT-1]  78.57 83 0 top
HOLE6  *h-s157d157n  [H-S157D157N]  121.49 76.98 0 top
HOLE8  *H-TC154IC154BC237D154PT-1  [H-TC154IC154BC237D154PT-1]  117.22 57 0 top
HOLE9  *spad-re209x315np  [SPAD-RE209X315NP]  215.74 37.1 0 top
HOLE10  *H-TC154IC154BC237D154PT-1  [H-TC154IC154BC237D154PT-1]  78.57 31 0 top
HOLE11  *spad-c354np  [SPAD-C354NP]  140.49 22.1 0 top
HOLE12  *spad-c354np  [SPAD-C354NP]  41.2 10 0 top
HOLE13  EV@H-C256I186D102P2  [H-C256I186D102P2]  97.53 123.31 180 bottom
HOLE14  *hg-o335x315d252x232p2  [HG-O335X315D252X232P2]  11.25 109.2 180 bottom
HOLE15  *SPAD-RE3_5X5_0  [SPAD-RE3_5X5_0]  3.35 108.2 180 bottom
HOLE16  *2D-BARCODE-8X8-S  [2D-BARCODE-8X8-S]  20.37 103.26 90 bottom
HOLE17  EV@H-C256I186D102P2  [H-C256I186D102P2]  126.53 84.31 180 bottom
HOLE18  *hg-c354i158d118p2  [HG-C354I158D118P2]  17.48 68.15 180 bottom
HOLE19  *HG-C276D126P2  [HG-C276D126P2]  221.2 48.5 180 bottom
HOLE20  *h-c75d75n  [H-C75D75N]  4.2 24 180 bottom
HOLE21  h-davidoff-1  [H-DAVIDOFF-1]  216.8 21.88 180 bottom
HOLE22  *HG-Z8E-EDADOC-3  [HG-Z8E-EDADOC-3]  86.2 15.5 180 bottom
HOLE23  *H-DAVIDOFF-1-1  [H-DAVIDOFF-1-1]  5.2 4.4 180 bottom
J1  *JUMP  [JOPEN25X30_S]  64.07 25.26 180 bottom
L1  BLM15AG601SN1D  [R0402]  41.59 113.91 270 top
L2  BLM15AG601SN1D  [R0402]  42.61 113.91 270 top
L3  BLM15AG121SN1D  [R0402]  166.56 31.86 270 top
L4  HCB2012KF-220T60  [R0805]  203.01 28.94 270 top
